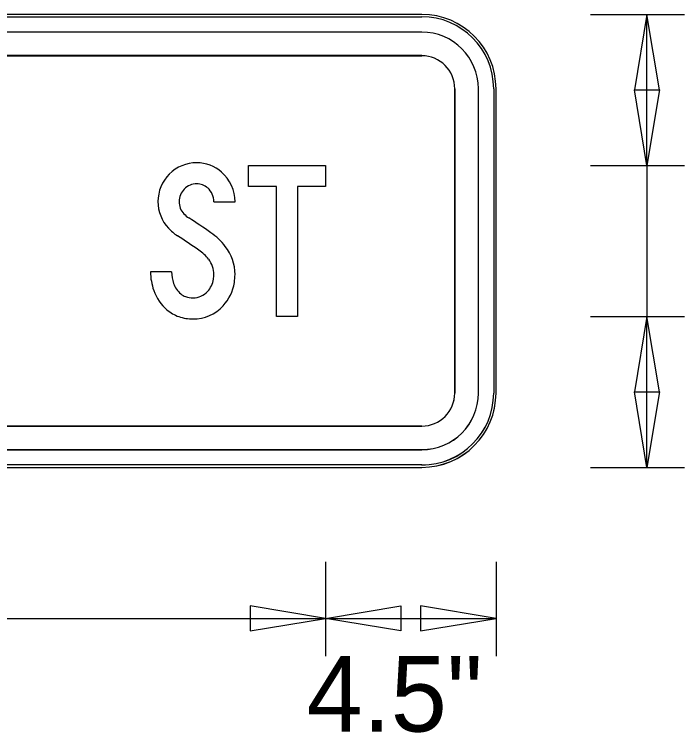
# Model space of a CAD drawing. Extents: x 57.2 to 85.4, y 153.3 to 173.4.
# Drawn here: x 80.344 to 81.825, y 169.257 to 170.843 of the extents above; entities that cross this region are included whole.
import ezdxf

# ---------------------------------------------------------------- set-up
doc = ezdxf.new("R2010")
doc.units = 0
for name, color, linetype in [('GSBWFILL', 7, 'Continuous'), ('GSCOLORFILL', 7, 'Continuous'), ('GSDIMS', 7, 'Continuous'), ('GSOUTLINE', 7, 'Continuous')]:
    doc.layers.add(name, color=color, linetype=linetype)

msp = doc.modelspace()

# ---------------------------------------------------------------- linework, layer by layer
at = {"layer": 'GSBWFILL'}
for p, q in [((81.2439, 170.8428), (79.0721, 170.8428)), ((81.2439, 170.8428), (79.0721, 170.8428)), ((81.2439, 170.8037), (79.0721, 170.8037)), ((81.2439, 170.8037), (79.0721, 170.8037)), ((79.0721, 170.7517), (81.2439, 170.7517)), ((79.0721, 170.7516), (81.2439, 170.7516)), ((81.3168, 170.6787), (81.3168, 170.0069)), ((81.3168, 170.6787), (81.3168, 170.0068)), ((81.3689, 170.0069), (81.3689, 170.6787)), ((81.3689, 170.0068), (81.3689, 170.6787)), ((81.408, 170.0069), (81.408, 170.6787)), ((81.408, 170.0068), (81.408, 170.6787)), ((81.2439, 169.934), (79.0726, 169.934)), ((81.2439, 169.9339), (79.0726, 169.9339)), ((79.0726, 169.8819), (81.2439, 169.8819)), ((79.0726, 169.8818), (81.2439, 169.8818)), ((79.0721, 169.8428), (81.2439, 169.8428)), ((79.0721, 169.8428), (81.2439, 169.8428))]:
    msp.add_line(p, q, dxfattribs=at)
msp.add_lwpolyline([(80.923, 170.4628), (80.8613, 170.4628), (80.8613, 170.5095), (81.0313, 170.5095), (81.0313, 170.4628), (80.9696, 170.4628), (80.9696, 170.1761), (80.923, 170.1761)], close=True, dxfattribs=at)
for points in [[(80.7846, 170.4292), (80.8313, 170.4292)], [(80.6913, 170.2742), (80.6446, 170.2742)]]:
    msp.add_lwpolyline(points, dxfattribs=at)
for centre, radius, start, end in [((81.2439, 170.6787), 0.1641, 0, 90), ((81.2439, 170.6787), 0.1641, 0, 90), ((81.2439, 170.6787), 0.125, 0, 90), ((81.2439, 170.6787), 0.125, 0, 90), ((81.2439, 170.6787), 0.0729, 0, 90), ((81.2439, 170.6787), 0.0729, 0, 90), ((81.2439, 170.0069), 0.125, 270, 0), ((81.2439, 170.0069), 0.0729, 270, 0), ((81.2439, 170.0069), 0.1641, 270, 0), ((81.2439, 170.0068), 0.125, 270, 0), ((81.2439, 170.0068), 0.0729, 270, 0), ((81.2439, 170.0068), 0.1641, 270, 0)]:
    msp.add_arc(centre, radius, start, end, dxfattribs=at)
for centre, major_axis, start_param, end_param in [((80.7469, 170.4294), (0, 0.0859), 6.283184, 7.853982), ((80.7469, 170.4323), (0, 0.0829), 5.561989, 6.283185), ((80.7442, 170.4292), (0, 0.0871), 4.712389, 5.561989), ((80.7469, 170.4294), (0, 0.0392), 6.283183, 7.853981), ((80.7469, 170.4323), (0, 0.0363), 5.561989, 6.283185), ((80.7442, 170.4292), (0, 0.0405), 4.712389, 5.561989), ((80.7471, 170.4294), (0, 0.086), 1.570796, 2.321595), ((80.7471, 170.4294), (0, 0.0394), 1.570796, 2.321595), ((80.7613, 170.4427), (0, 0.0588), 2.321595, 2.56746), ((79.6639, 168.746), (0, 1.9619), 5.679143, 5.709053), ((80.7613, 170.4427), (0, 0.1054), 2.321595, 2.56746), ((79.6639, 168.746), (0, 1.9152), 5.679143, 5.709053), ((80.6966, 170.2426), (0, 0.1435), 5.373599, 5.679143), ((80.6966, 170.2426), (0, 0.0969), 5.373599, 5.679143), ((80.7298, 170.2684), (0, 0.1015), 4.712389, 5.373599), ((80.7298, 170.2684), (0, 0.0549), 4.712389, 5.373599), ((80.7676, 170.2742), (0, 0.1229), 1.570808, 1.909921), ((80.7676, 170.2742), (0, 0.0763), 1.570816, 1.909918), ((80.7203, 170.2684), (0, 0.0643), 4.552917, 4.712389), ((80.7203, 170.2684), (0, 0.111), 4.552917, 4.712389), ((80.7322, 170.2665), (0, 0.0523), 3.967076, 4.552917), ((80.7465, 170.2668), (0, 0.0539), 1.909925, 2.431476), ((80.7322, 170.2665), (0, 0.099), 3.967076, 4.552917), ((80.7465, 170.2668), (0, 0.1006), 1.909925, 2.431476), ((80.7329, 170.2509), (0, 0.033), 2.431476, 2.811358), ((80.7386, 170.2605), (0, 0.0435), 3.141593, 3.967076), ((80.7386, 170.2678), (0, 0.0508), 2.811358, 3.141593), ((80.7329, 170.2509), (0, 0.0796), 2.431476, 2.811358), ((80.7386, 170.2605), (0, 0.0902), 3.141593, 3.967076), ((80.7386, 170.2678), (0, 0.0975), 2.811358, 3.141593)]:
    msp.add_ellipse(centre, major_axis=major_axis, ratio=0.999991, start_param=start_param, end_param=end_param, dxfattribs=at)
at = {"layer": 'GSCOLORFILL'}
for p, q in [((81.2439, 170.8428), (79.0721, 170.8428)), ((81.2439, 170.8428), (79.0721, 170.8428)), ((81.2439, 170.8428), (79.0721, 170.8428)), ((81.2439, 170.8428), (79.0721, 170.8428)), ((79.0721, 170.8376), (81.2439, 170.8376)), ((79.0721, 170.8376), (81.2439, 170.8376)), ((81.2439, 170.8037), (79.0721, 170.8037)), ((81.2439, 170.8037), (79.0721, 170.8037)), ((79.0721, 170.7517), (81.2439, 170.7517)), ((79.0721, 170.7516), (81.2439, 170.7516)), ((81.3168, 170.6787), (81.3168, 170.0069)), ((81.3168, 170.6787), (81.3168, 170.0068)), ((81.3689, 170.0069), (81.3689, 170.6787)), ((81.3689, 170.0068), (81.3689, 170.6787)), ((81.4028, 170.6787), (81.4028, 170.0069)), ((81.4028, 170.6787), (81.4028, 170.0068)), ((81.408, 170.0069), (81.408, 170.6787)), ((81.408, 170.0069), (81.408, 170.6787)), ((81.408, 170.0068), (81.408, 170.6787)), ((81.408, 170.0068), (81.408, 170.6787)), ((81.2439, 169.934), (79.0726, 169.934)), ((81.2439, 169.9339), (79.0726, 169.9339)), ((79.0726, 169.8819), (81.2439, 169.8819)), ((79.0726, 169.8818), (81.2439, 169.8818)), ((81.2439, 169.848), (79.0721, 169.848)), ((81.2439, 169.848), (79.0721, 169.848)), ((79.0721, 169.8428), (81.2439, 169.8428)), ((79.0721, 169.8428), (81.2439, 169.8428)), ((79.0721, 169.8428), (81.2439, 169.8428)), ((79.0721, 169.8428), (81.2439, 169.8428))]:
    msp.add_line(p, q, dxfattribs=at)
msp.add_lwpolyline([(80.923, 170.4628), (80.8613, 170.4628), (80.8613, 170.5095), (81.0313, 170.5095), (81.0313, 170.4628), (80.9696, 170.4628), (80.9696, 170.1761), (80.923, 170.1761)], close=True, dxfattribs=at)
for points in [[(80.7846, 170.4292), (80.8313, 170.4292)], [(80.6913, 170.2742), (80.6446, 170.2742)]]:
    msp.add_lwpolyline(points, dxfattribs=at)
for centre, radius, start, end in [((81.2439, 170.6787), 0.1641, 0, 90), ((81.2439, 170.6787), 0.1641, 0, 90), ((81.2439, 170.6787), 0.1641, 0, 90), ((81.2439, 170.6787), 0.1641, 0, 90), ((81.2439, 170.6787), 0.1589, 0, 90), ((81.2439, 170.6787), 0.1589, 0, 90), ((81.2439, 170.6787), 0.125, 0, 90), ((81.2439, 170.6787), 0.125, 0, 90), ((81.2439, 170.6787), 0.0729, 0, 90), ((81.2439, 170.6787), 0.0729, 0, 90), ((81.2439, 170.0069), 0.1641, 270, 0), ((81.2439, 170.0069), 0.125, 270, 0), ((81.2439, 170.0069), 0.0729, 270, 0), ((81.2439, 170.0069), 0.1641, 270, 0), ((81.2439, 170.0069), 0.1589, 270, 0), ((81.2439, 170.0068), 0.1641, 270, 0), ((81.2439, 170.0068), 0.125, 270, 0), ((81.2439, 170.0068), 0.0729, 270, 0), ((81.2439, 170.0068), 0.1641, 270, 0), ((81.2439, 170.0068), 0.1589, 270, 0)]:
    msp.add_arc(centre, radius, start, end, dxfattribs=at)
for centre, major_axis, start_param, end_param in [((80.7469, 170.4294), (0, 0.0859), 6.283184, 7.853982), ((80.7469, 170.4323), (0, 0.0829), 5.561989, 6.283185), ((80.7442, 170.4292), (0, 0.0871), 4.712389, 5.561989), ((80.7469, 170.4294), (0, 0.0392), 6.283183, 7.853981), ((80.7469, 170.4323), (0, 0.0363), 5.561989, 6.283185), ((80.7442, 170.4292), (0, 0.0405), 4.712389, 5.561989), ((80.7471, 170.4294), (0, 0.086), 1.570796, 2.321595), ((80.7471, 170.4294), (0, 0.0394), 1.570796, 2.321595), ((80.7613, 170.4427), (0, 0.0588), 2.321595, 2.56746), ((79.6639, 168.746), (0, 1.9619), 5.679143, 5.709053), ((80.7613, 170.4427), (0, 0.1054), 2.321595, 2.56746), ((79.6639, 168.746), (0, 1.9152), 5.679143, 5.709053), ((80.6966, 170.2426), (0, 0.1435), 5.373599, 5.679143), ((80.6966, 170.2426), (0, 0.0969), 5.373599, 5.679143), ((80.7298, 170.2684), (0, 0.1015), 4.712389, 5.373599), ((80.7298, 170.2684), (0, 0.0549), 4.712389, 5.373599), ((80.7676, 170.2742), (0, 0.1229), 1.570808, 1.909921), ((80.7676, 170.2742), (0, 0.0763), 1.570816, 1.909918), ((80.7203, 170.2684), (0, 0.0643), 4.552917, 4.712389), ((80.7203, 170.2684), (0, 0.111), 4.552917, 4.712389), ((80.7322, 170.2665), (0, 0.0523), 3.967076, 4.552917), ((80.7465, 170.2668), (0, 0.0539), 1.909925, 2.431476), ((80.7322, 170.2665), (0, 0.099), 3.967076, 4.552917), ((80.7465, 170.2668), (0, 0.1006), 1.909925, 2.431476), ((80.7329, 170.2509), (0, 0.033), 2.431476, 2.811358), ((80.7386, 170.2605), (0, 0.0435), 3.141593, 3.967076), ((80.7386, 170.2678), (0, 0.0508), 2.811358, 3.141593), ((80.7329, 170.2509), (0, 0.0796), 2.431476, 2.811358), ((80.7386, 170.2605), (0, 0.0902), 3.141593, 3.967076), ((80.7386, 170.2678), (0, 0.0975), 2.811358, 3.141593)]:
    msp.add_ellipse(centre, major_axis=major_axis, ratio=0.999991, start_param=start_param, end_param=end_param, dxfattribs=at)
at = {"layer": 'GSDIMS'}
for p, q in [((81.6164, 170.8429), (81.8247, 170.8429)), ((81.6164, 170.8429), (81.6164, 170.8429)), ((81.7414, 170.5095), (81.7414, 170.8429)), ((81.6164, 170.5095), (81.8247, 170.5095)), ((81.6164, 170.5095), (81.8247, 170.5095)), ((81.7414, 170.5095), (81.7414, 170.1761)), ((81.6164, 170.1761), (81.8247, 170.1761)), ((81.6164, 170.1761), (81.8247, 170.1761)), ((81.7414, 169.8428), (81.7414, 170.1761)), ((81.6164, 169.8428), (81.8247, 169.8428)), ((81.6164, 169.8428), (81.6164, 169.8428)), ((81.0314, 169.6344), (81.0314, 169.4261)), ((81.0314, 169.6344), (81.0314, 169.4261)), ((81.408, 169.6344), (81.408, 169.4261)), ((81.408, 169.6344), (81.408, 169.4261)), ((79.2846, 169.5094), (81.0314, 169.5094)), ((81.0314, 169.5094), (81.408, 169.5094))]:
    msp.add_line(p, q, dxfattribs=at)
for points in [[(81.7414, 170.8429), (81.7136, 170.6762), (81.7691, 170.6762)], [(81.7414, 170.5095), (81.7136, 170.6761), (81.7691, 170.6761)], [(81.7414, 170.1761), (81.7136, 170.0095), (81.7691, 170.0095)], [(81.7414, 169.8428), (81.7136, 170.0094), (81.7691, 170.0094)], [(81.0314, 169.5094), (80.8647, 169.5372), (80.8647, 169.4817)], [(81.0314, 169.5094), (81.198, 169.5372), (81.198, 169.4817)], [(81.408, 169.5094), (81.2414, 169.5372), (81.2414, 169.4817)]]:
    msp.add_lwpolyline(points, close=True, dxfattribs=at)
at = {"layer": 'GSOUTLINE'}
for p, q in [((81.2439, 170.8428), (79.0721, 170.8428)), ((81.2439, 170.8428), (79.0721, 170.8428)), ((81.2439, 170.8037), (79.0721, 170.8037)), ((81.2439, 170.8037), (79.0721, 170.8037)), ((81.2439, 170.7517), (79.0721, 170.7517)), ((81.2439, 170.7516), (79.0721, 170.7516)), ((81.3168, 170.0069), (81.3168, 170.6787)), ((81.3168, 170.0068), (81.3168, 170.6787)), ((81.3689, 170.0069), (81.3689, 170.6787)), ((81.3689, 170.0068), (81.3689, 170.6787)), ((81.408, 170.0069), (81.408, 170.6787)), ((81.408, 170.0068), (81.408, 170.6787)), ((79.0721, 169.934), (81.2439, 169.934)), ((79.0721, 169.9339), (81.2439, 169.9339)), ((79.0721, 169.8819), (81.2439, 169.8819)), ((79.0721, 169.8818), (81.2439, 169.8818)), ((79.0721, 169.8428), (81.2439, 169.8428)), ((79.0721, 169.8428), (81.2439, 169.8428))]:
    msp.add_line(p, q, dxfattribs=at)
msp.add_lwpolyline([(80.923, 170.4628), (80.8613, 170.4628), (80.8613, 170.5095), (81.0313, 170.5095), (81.0313, 170.4628), (80.9696, 170.4628), (80.9696, 170.1761), (80.923, 170.1761)], close=True, dxfattribs=at)
for points in [[(80.7846, 170.4292), (80.8313, 170.4292)], [(80.6913, 170.2742), (80.6446, 170.2742)]]:
    msp.add_lwpolyline(points, dxfattribs=at)
for centre, radius, start, end in [((81.2439, 170.6787), 0.1641, 0, 90), ((81.2439, 170.6787), 0.1641, 0, 90), ((81.2439, 170.6787), 0.125, 0, 90), ((81.2439, 170.6787), 0.125, 0, 90), ((81.2439, 170.6787), 0.0729, 0, 90), ((81.2439, 170.6787), 0.0729, 0, 90), ((81.2439, 170.0069), 0.125, 270, 0), ((81.2439, 170.0069), 0.0729, 270, 0), ((81.2439, 170.0069), 0.1641, 270, 0), ((81.2439, 170.0068), 0.125, 270, 0), ((81.2439, 170.0068), 0.0729, 270, 0), ((81.2439, 170.0068), 0.1641, 270, 0)]:
    msp.add_arc(centre, radius, start, end, dxfattribs=at)
for centre, major_axis, start_param, end_param in [((80.7469, 170.4294), (0, 0.0859), 6.283184, 7.853982), ((80.7469, 170.4323), (0, 0.0829), 5.561989, 6.283185), ((80.7442, 170.4292), (0, 0.0871), 4.712389, 5.561989), ((80.7469, 170.4294), (0, 0.0392), 6.283183, 7.853981), ((80.7469, 170.4323), (0, 0.0363), 5.561989, 6.283185), ((80.7442, 170.4292), (0, 0.0405), 4.712389, 5.561989), ((80.7471, 170.4294), (0, 0.086), 1.570796, 2.321595), ((80.7471, 170.4294), (0, 0.0394), 1.570796, 2.321595), ((80.7613, 170.4427), (0, 0.0588), 2.321595, 2.56746), ((79.6639, 168.746), (0, 1.9619), 5.679143, 5.709053), ((80.7613, 170.4427), (0, 0.1054), 2.321595, 2.56746), ((79.6639, 168.746), (0, 1.9152), 5.679143, 5.709053), ((80.6966, 170.2426), (0, 0.1435), 5.373599, 5.679143), ((80.6966, 170.2426), (0, 0.0969), 5.373599, 5.679143), ((80.7298, 170.2684), (0, 0.1015), 4.712389, 5.373599), ((80.7298, 170.2684), (0, 0.0549), 4.712389, 5.373599), ((80.7676, 170.2742), (0, 0.1229), 1.570808, 1.909921), ((80.7676, 170.2742), (0, 0.0763), 1.570816, 1.909918), ((80.7203, 170.2684), (0, 0.0643), 4.552917, 4.712389), ((80.7203, 170.2684), (0, 0.111), 4.552917, 4.712389), ((80.7322, 170.2665), (0, 0.0523), 3.967076, 4.552917), ((80.7465, 170.2668), (0, 0.0539), 1.909925, 2.431476), ((80.7322, 170.2665), (0, 0.099), 3.967076, 4.552917), ((80.7465, 170.2668), (0, 0.1006), 1.909925, 2.431476), ((80.7329, 170.2509), (0, 0.033), 2.431476, 2.811358), ((80.7386, 170.2605), (0, 0.0435), 3.141593, 3.967076), ((80.7386, 170.2678), (0, 0.0508), 2.811358, 3.141593), ((80.7329, 170.2509), (0, 0.0796), 2.431476, 2.811358), ((80.7386, 170.2605), (0, 0.0902), 3.141593, 3.967076), ((80.7386, 170.2678), (0, 0.0975), 2.811358, 3.141593)]:
    msp.add_ellipse(centre, major_axis=major_axis, ratio=0.999991, start_param=start_param, end_param=end_param, dxfattribs=at)

# ---------------------------------------------------------------- texts
at = {"layer": 'GSDIMS'}
msp.add_text('4.5"', height=0.16667, dxfattribs=at).set_placement((80.9895, 169.2594))

doc.saveas('drawing.dxf')
